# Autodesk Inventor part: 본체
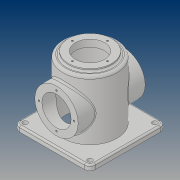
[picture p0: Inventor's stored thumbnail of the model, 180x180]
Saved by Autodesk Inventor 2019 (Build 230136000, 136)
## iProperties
Created: 2019-03
Part Number: 본체
Material: 일반
Document SubType Name: Modeling
Designer: PC312-13
Density: 1 g/cm^3
Appearance: 기본값
Author: PC312-13
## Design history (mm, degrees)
sketch "스케치1"
  geometry: C1 r 50 at (0, 0); 1 further point
  constraints: 1 centre point, 1 coincident
  dimensions: "d0" = 100 diameter of C1
extrude "돌출1" new body sketch "스케치1" distance "d1" = 120; taper "d2" = 0 deg
sketch "스케치2"
  geometry: C1 r 45 at (0, 0); 1 further point
  constraints: 1 centre point, 1 coincident
  dimensions: "d3" = 90 diameter of C1
extrude "돌출2" cut sketch "스케치2" distance "d4" = 112; taper "d5" = 0 deg
sketch "스케치3"
  geometry: L1 (-70, -70)-(70, -70); L2 (70, -70)-(70, 70); L3 (70, 70)-(-70, 70); L4 (-70, 70)-(-70, -70); L5 (-70, -70)-(70, 70); L6 (70, -70)-(-70, 70); C1 r 45 at (0, 0) reference; 1 further point
  constraints: 12 end point, 2 midpoint, 2 parallel, 1 horizontal, 1 perpendicular
  dimensions: "d6" = 140 distance of L3.end L2.end; "d7" = 140 distance of L1.end L2.end
extrude "돌출3" join sketch "스케치3" distance "d8" = 10; taper "d9" = 0 deg
sketch "스케치4"
  geometry: C1 r 40 at (0, 0); 1 further point
  constraints: 1 centre point, 1 coincident
  dimensions: "d10" = 80 diameter of C1
extrude "돌출4" join sketch "스케치4" distance "d11" = 5; taper "d12" = 0 deg
sketch "스케치5"
  geometry: C1 r 27 at (0, 0); 1 further point
  constraints: 1 centre point, 1 coincident
  dimensions: "d13" = 54 diameter of C1
extrude "돌출5" cut sketch "스케치5" extent not by distance; stored distance "d14" = 5; taper "d15" = 0 deg
node "작업 평면1"
sketch "스케치6"
  geometry: L1 (70, 0)-(-70, 0) reference; C1 r 40 at (0, 60); 2 further points
  constraints: 1 centre point, 1 midpoint, 1 vertical alignment
  dimensions: "d17" = 80 diameter of C1; "d18" = 60 distance from line of L1 C1.centre
extrude "돌출6" join sketch "스케치6" stored distance "d19" = 5; taper "d20" = 0 deg
sketch "스케치7"
  geometry: C1 r 40 at (0, 0) reference; 2 further points
  constraints: 1 vertical alignment
  dimensions: "d21" = 32.5 distance of point (0, 32.5) C1.centre
hole "구멍1" sketch "스케치7" at (0, 32.5) diameter "d22" = 3.242; stored, may be unused: countersink angle "d26" = 90 deg, drill point angle "d28" = 118 deg; dims "d23" = 8, "d24" = 4, "d25" = 2, "d27" = 10
fillet "모깎기1" dims "d32" = 10
fillet "모깎기2" dims "d33" = 5
fillet "모깎기3" dims "d34" = 3
sketch "스케치8"
  geometry: 2 further points
  constraints: 1 vertical alignment
  dimensions: "d35" = 32.5 distance of point (0, 32.5) point (0, 0)
hole "구멍2" sketch "스케치8" at (0, 32.5) diameter "d36" = 3.242; stored, may be unused: countersink angle "d40" = 90 deg, drill point angle "d42" = 118 deg; dims "d37" = 8, "d38" = 4, "d39" = 2, "d41" = 10
sketch "스케치9"
  geometry: C1 r 1.621 at (-32.5, 0) reference; C2 r 1.621 at (0, -32.5) reference; C3 r 1.621 at (32.5, 0) reference; C4 r 1.621 at (0, 32.5) reference; C5 r 40 at (0, 0) reference; C6 r 27 at (0, 0); 1 further point
  constraints: 1 centre point, 1 coincident
  dimensions: "d46" = 54 diameter of C6
extrude "돌출7" cut sketch "스케치9" extent not by distance; stored distance "d47" = 0; taper "d48" = 0 deg
sketch "스케치10"
  geometry: A1 r 10 centre (-60, -60) between (-70, -60) and (-60, -70) reference; 2 further points
  constraints: 1 coincident
hole "구멍3" sketch "스케치10" at (-60, -60) diameter "d49" = 9; stored, may be unused: countersink angle "d53" = 90 deg, drill point angle "d55" = 0 deg; dims "d50" = 8, "d51" = 4, "d52" = 2, "d54" = 10
fillet "모깎기4" dims "d62" = 3
node "솔리드1"
pattern_circular "원형 패턴1" dims angle "d30" = 360 deg
mirror "미러1"
pattern_circular "원형 패턴2" dims angle "d44" = 360 deg
pattern_linear "직사각형 패턴1" dims "d58" = 120, "d61" = 120
node "투영된 루프1"
node "투영된 루프2"
other parameters: "d16" = 62
